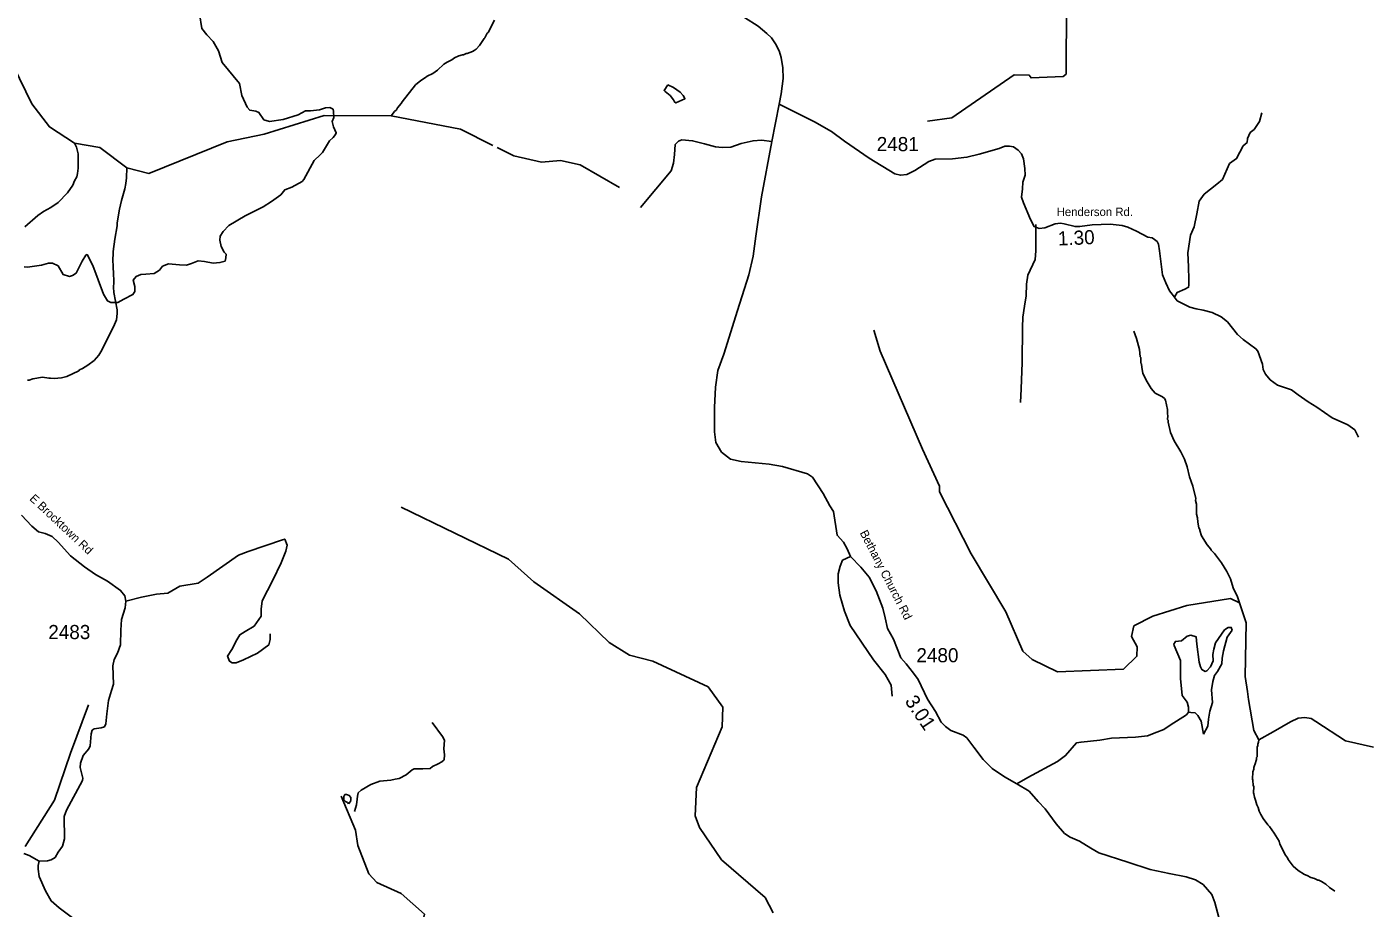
# Model space of a CAD drawing. Extents: x 1248224 to 1454986, y 825081 to 985870.
# Drawn here: x 1367503 to 1379404, y 843465 to 851257 of the extents above; entities that cross this region are included whole.
import ezdxf

# ---------------------------------------------------------------- set-up
doc = ezdxf.new("R2010")
doc.units = 0
for name, color, linetype in [('Exist Hydrographic Creek Single Shore', 7, 'Continuous'), ('Exist Hydrographic Misc Water Feature', 7, 'Continuous'), ('Exist Road Non-System Type 51', 7, 'Continuous'), ('Exist Road Secondary Mileage Hundredths English Label', 7, 'Continuous'), ('Exist Road Secondary Type 41 Attributed', 7, 'Continuous'), ('Exist Road Secondary Type 51 Attributed', 7, 'Continuous'), ('Exist Road Secondary Type 51 Label', 7, 'Continuous'), ('Exist Road Secondary Type 51 Number Label', 7, 'Continuous')]:
    doc.layers.add(name, color=color, linetype=linetype)

msp = doc.modelspace()

# ---------------------------------------------------------------- linework, layer by layer
at = {"layer": 'Exist Hydrographic Creek Single Shore'}
for points in [[(1375464, 850424), (1375681, 850452), (1376231, 850832), (1376364, 850829), (1376381, 850806), (1376664, 850817), (1376690, 850839), (1376694, 851466), (1376756, 851606), (1376925, 851737), (1377506, 852014), (1377613, 852347), (1377809, 852553), (1378241, 852899), (1378437, 853056), (1378476, 853321), (1378519, 853412), (1378866, 853632), (1378977, 853754), (1379062, 854027), (1379105, 854084)], [(1371622, 850209), (1371337, 850352), (1370723, 850470), (1370131, 850472), (1369602, 850309), (1369275, 850240), (1368582, 849960), (1368386, 850010), (1368148, 850190), (1367924, 850229), (1367702, 850373), (1367548, 850576), (1367221, 851243)]]:
    msp.add_lwpolyline(points, dxfattribs=at)
at = {"layer": 'Exist Hydrographic Misc Water Feature'}
for points in [[(1371637, 851315), (1371580, 851207), (1371572, 851201), (1371553, 851161), (1371545, 851154), (1371505, 851093), (1371475, 851061), (1371458, 851048), (1371442, 851040), (1371394, 851021), (1371386, 851021), (1371362, 851010), (1371354, 851010), (1371323, 851001), (1371283, 850982), (1371260, 850966), (1371218, 850945), (1371188, 850926), (1371134, 850873), (1371092, 850846), (1371043, 850822), (1371027, 850808), (1370986, 850783), (1370939, 850744), (1370820, 850595), (1370812, 850579), (1370779, 850540), (1370770, 850524), (1370754, 850509), (1370723, 850470)], [(1373170, 850746), (1373136, 850695), (1373145, 850685), (1373190, 850649), (1373219, 850613), (1373229, 850594), (1373241, 850584), (1373321, 850622), (1373314, 850636), (1373306, 850649), (1373277, 850679), (1373219, 850721), (1373170, 850746)], [(1367486, 849490), (1367600, 849588), (1367649, 849623), (1367714, 849661), (1367779, 849705), (1367863, 849789), (1367908, 849856), (1367925, 849896), (1367944, 849930), (1367951, 849959), (1367956, 850007), (1367957, 850135), (1367942, 850192), (1367924, 850229)], [(1372054, 850062), (1371807, 850117), (1371662, 850189)], [(1367507, 848132), (1367523, 848134), (1367556, 848145), (1367642, 848159), (1367696, 848150), (1367712, 848151), (1367744, 848149), (1367808, 848155), (1367856, 848166), (1367961, 848215), (1367969, 848223), (1367994, 848235), (1368042, 848265), (1368097, 848308), (1368139, 848355), (1368157, 848383), (1368178, 848422), (1368191, 848454), (1368268, 848604), (1368287, 848646), (1368294, 848667), (1368301, 848723), (1368302, 848755), (1368273, 848908), (1368270, 848956), (1368273, 848996), (1368272, 849036), (1368268, 849052), (1368267, 849156), (1368263, 849180), (1368265, 849270), (1368280, 849380), (1368301, 849499), (1368301, 849523), (1368322, 849645), (1368340, 849722), (1368370, 849825), (1368379, 849873), (1368384, 849921), (1368386, 850010)], [(1372742, 849838), (1372395, 850036), (1372221, 850075), (1372054, 850062)], [(1379409, 844888), (1379160, 844943), (1378897, 845115), (1378856, 845142), (1378801, 845151), (1378743, 845144), (1378675, 845113), (1378520, 845024), (1378395, 844951), (1378351, 845036), (1378303, 845308), (1378294, 845380), (1378272, 845512), (1378282, 845988), (1378224, 846165), (1378144, 846201), (1377759, 846140), (1377457, 846047), (1377289, 845959), (1377270, 845867), (1377318, 845774), (1377317, 845692), (1377197, 845576), (1376613, 845555), (1376391, 845662), (1376309, 845735), (1376157, 846083), (1375851, 846598), (1375571, 847145), (1375572, 847195), (1375420, 847523), (1375046, 848390), (1374992, 848575)], [(1377289, 848566), (1377312, 848501), (1377339, 848404), (1377346, 848340), (1377350, 848332), (1377352, 848284), (1377356, 848276), (1377359, 848244), (1377370, 848196), (1377397, 848133), (1377441, 848060), (1377478, 848019), (1377502, 848005), (1377543, 847986), (1377559, 847971), (1377568, 847955), (1377587, 847874), (1377586, 847835), (1377589, 847818), (1377588, 847786), (1377592, 847778), (1377592, 847762), (1377614, 847670), (1377646, 847597), (1377704, 847500), (1377736, 847435), (1377760, 847366), (1377780, 847278), (1377810, 847197), (1377836, 847085), (1377835, 847069), (1377842, 847036), (1377844, 846948), (1377852, 846916), (1377855, 846876), (1377865, 846828), (1377873, 846812), (1377873, 846804), (1377888, 846757), (1377938, 846676), (1377971, 846637), (1377973, 846631), (1378002, 846601), (1378064, 846519), (1378112, 846442), (1378143, 846377), (1378167, 846297), (1378207, 846216), (1378224, 846165)], [(1371985, 846351), (1371762, 846549), (1370813, 847011)], [(1374101, 843423), (1374029, 843559), (1373644, 843892), (1373450, 844178), (1373410, 844280), (1373424, 844530), (1373651, 845067), (1373655, 845241), (1373525, 845420), (1373038, 845647), (1372831, 845700), (1372650, 845812), (1372388, 846067), (1371985, 846351)], [(1367487, 844009), (1367746, 844420), (1367888, 844835), (1368048, 845261)], [(1379067, 843614), (1379020, 843648), (1378988, 843676), (1378949, 843699), (1378925, 843710), (1378917, 843710), (1378886, 843727), (1378854, 843736), (1378822, 843752), (1378798, 843761), (1378741, 843798), (1378698, 843836), (1378655, 843893), (1378648, 843909), (1378630, 843933), (1378581, 844030), (1378573, 844055), (1378531, 844128), (1378490, 844185), (1378475, 844201), (1378432, 844258), (1378411, 844291), (1378396, 844323), (1378388, 844355), (1378377, 844379), (1378366, 844420), (1378355, 844444), (1378351, 844476), (1378348, 844484), (1378349, 844540), (1378345, 844548), (1378342, 844596), (1378338, 844604), (1378340, 844668), (1378349, 844692), (1378349, 844708), (1378357, 844724), (1378358, 844732), (1378375, 844779), (1378375, 844795), (1378379, 844803), (1378381, 844891), (1378386, 844899), (1378386, 844915), (1378392, 844931), (1378395, 844951)], [(1371885, 841911), (1371810, 841936), (1371705, 842072), (1371465, 842169), (1371106, 842528), (1370795, 842777), (1370764, 842876), (1370971, 843207), (1371017, 843412), (1370813, 843594), (1370598, 843690), (1370525, 843767), (1370430, 844019), (1370408, 844154), (1370282, 844455)], [(1370345, 844387), (1370337, 844397), (1370319, 844408), (1370306, 844422), (1370305, 844452), (1370315, 844468), (1370329, 844469), (1370337, 844467), (1370353, 844459), (1370366, 844441), (1370368, 844423), (1370363, 844407), (1370345, 844387)], [(1370345, 844387), (1370337, 844397), (1370319, 844408), (1370306, 844422), (1370305, 844452), (1370315, 844468), (1370329, 844469), (1370337, 844467), (1370353, 844459), (1370366, 844441), (1370368, 844423), (1370363, 844407), (1370345, 844387)]]:
    msp.add_lwpolyline(points, dxfattribs=at)
at = {"layer": 'Exist Road Non-System Type 51'}
for points in [[(1369029, 851372), (1369049, 851242), (1369095, 851188), (1369150, 851127), (1369196, 851046), (1369230, 850942), (1369382, 850756), (1369402, 850650), (1369451, 850546), (1369474, 850520), (1369526, 850511), (1369555, 850500), (1369598, 850436), (1369647, 850419), (1369768, 850439), (1369901, 850480), (1369965, 850514), (1370011, 850514), (1370091, 850523), (1370143, 850540), (1370181, 850543), (1370210, 850529), (1370215, 850508), (1370218, 850456), (1370201, 850419), (1370215, 850373), (1370238, 850321), (1370230, 850304), (1370212, 850278), (1370178, 850249), (1370117, 850146), (1370097, 850126), (1370042, 850074), (1369950, 849906), (1369936, 849889), (1369846, 849840), (1369783, 849817), (1369748, 849771), (1369665, 849713), (1369593, 849667), (1369434, 849586), (1369288, 849501), (1369239, 849449), (1369213, 849406), (1369210, 849371), (1369222, 849314), (1369247, 849265), (1369265, 849247), (1369262, 849216), (1369256, 849184)], [(1377651, 848873), (1377672, 848907), (1377741, 848939), (1377773, 848955), (1377776, 848972), (1377776, 849024), (1377773, 849135), (1377767, 849259), (1377789, 849415), (1377822, 849490), (1377845, 849604), (1377868, 849715), (1377910, 849777), (1378024, 849865), (1378073, 849908), (1378135, 850048), (1378197, 850093), (1378255, 850204), (1378291, 850235), (1378294, 850271), (1378317, 850323), (1378353, 850349), (1378395, 850411), (1378401, 850421), (1378421, 850496)], [(1374088, 850242), (1373998, 850256), (1373923, 850250), (1373818, 850227), (1373727, 850194), (1373649, 850191), (1373590, 850197), (1373493, 850223), (1373388, 850250), (1373294, 850259), (1373265, 850246), (1373235, 850217), (1373229, 850129), (1373219, 850051), (1373199, 849985), (1372929, 849659)], [(1376422, 849508), (1376423, 849452), (1376423, 849276), (1376416, 849201), (1376351, 849061), (1376341, 848983), (1376338, 848878), (1376322, 848787), (1376309, 848689), (1376305, 848598), (1376302, 848288), (1376292, 848057), (1376286, 847936)], [(1369256, 849184), (1369210, 849172), (1369149, 849169), (1369072, 849181), (1369017, 849187), (1368959, 849164), (1368913, 849149), (1368853, 849152), (1368755, 849161), (1368703, 849140), (1368674, 849106), (1368628, 849077), (1368556, 849071), (1368510, 849068), (1368469, 849051), (1368443, 849016), (1368458, 848962), (1368458, 848918), (1368440, 848890), (1368360, 848849), (1368308, 848820), (1368244, 848820), (1368216, 848833), (1368179, 848893), (1368087, 849147), (1368035, 849243), (1368024, 849239), (1367992, 849184), (1367940, 849080), (1367905, 849057), (1367879, 849051), (1367825, 849066), (1367779, 849143), (1367730, 849167), (1367695, 849167), (1367632, 849149), (1367508, 849132), (1367479, 849135)], [(1369655, 845889), (1369655, 845841), (1369641, 845792), (1369542, 845720), (1369418, 845659), (1369353, 845634), (1369319, 845634), (1369295, 845648), (1369278, 845693), (1369315, 845751), (1369360, 845837), (1369387, 845882), (1369432, 845909), (1369511, 845957), (1369573, 846047), (1369573, 846109), (1369583, 846181), (1369676, 846363), (1369751, 846517), (1369792, 846620), (1369803, 846675), (1369782, 846727), (1369762, 846720), (1369460, 846619), (1369374, 846584), (1369096, 846392), (1369017, 846337), (1368855, 846310), (1368749, 846248), (1368650, 846241), (1368516, 846213), (1368379, 846179)], [(1375153, 845338), (1375143, 845436), (1375090, 845531), (1374989, 845660), (1374781, 845963), (1374730, 846089), (1374689, 846231), (1374674, 846342), (1374674, 846421), (1374693, 846488), (1374715, 846541), (1374785, 846575)], [(1376255, 844564), (1376352, 844618), (1376613, 844760), (1376686, 844813), (1376782, 844925), (1376823, 844932), (1376988, 844950), (1377093, 844966), (1377303, 844975), (1377409, 844987), (1377493, 845019), (1377553, 845044), (1377610, 845083), (1377754, 845174), (1377772, 845197), (1377772, 845240), (1377761, 845286), (1377717, 845343), (1377701, 845495), (1377703, 845655), (1377646, 845786), (1377644, 845797), (1377657, 845822), (1377712, 845829), (1377762, 845868), (1377794, 845877), (1377840, 845864), (1377847, 845797), (1377868, 845639), (1377879, 845598), (1377890, 845573), (1377920, 845557), (1377936, 845562), (1377966, 845598), (1377991, 845651), (1377989, 845708), (1377996, 845754), (1378012, 845809), (1378092, 845925), (1378124, 845946), (1378151, 845946), (1378158, 845921), (1378114, 845859), (1378082, 845738), (1378069, 845674), (1378066, 845623), (1378028, 845557), (1378002, 845520), (1377989, 845468), (1377977, 845395), (1377984, 845282), (1377961, 845207), (1377948, 845134), (1377943, 845074), (1377904, 845002)], [(1370399, 844318), (1370418, 844378), (1370423, 844428), (1370425, 844453), (1370432, 844485), (1370459, 844508), (1370544, 844556), (1370624, 844586), (1370720, 844597), (1370759, 844604), (1370793, 844609), (1370857, 844643), (1370908, 844687), (1370926, 844696), (1371002, 844696), (1371068, 844700), (1371089, 844716), (1371139, 844739), (1371171, 844758), (1371192, 844776), (1371196, 844820), (1371189, 844874), (1371196, 844950), (1371178, 844982), (1371086, 845106)], [(1377904, 845002), (1377884, 845117), (1377854, 845169), (1377831, 845192), (1377794, 845195), (1377772, 845197)]]:
    msp.add_lwpolyline(points, dxfattribs=at)
at = {"layer": 'Exist Road Secondary Type 41 Attributed'}
for points in [[(1367455, 846940), (1367546, 846842), (1367606, 846791), (1367664, 846778), (1367728, 846750), (1367780, 846699), (1367889, 846580), (1368012, 846482), (1368110, 846413), (1368217, 846354), (1368331, 846274), (1368368, 846225), (1368379, 846179), (1368371, 846121), (1368340, 846016), (1368334, 845923), (1368330, 845792), (1368304, 845718), (1368275, 845663), (1368263, 845607), (1368270, 845446), (1368252, 845390), (1368224, 845301), (1368211, 845182), (1368202, 845095), (1368188, 845066), (1368160, 845059), (1368099, 845050), (1368081, 845037), (1368071, 845005), (1368063, 844898), (1368050, 844873), (1368001, 844815), (1367977, 844745), (1367974, 844708), (1367998, 844614), (1367994, 844594), (1367854, 844330), (1367833, 844273), (1367836, 844078), (1367817, 844011), (1367781, 843958), (1367753, 843913), (1367717, 843891), (1367686, 843882), (1367612, 843879)], [(1367612, 843879), (1367523, 843929), (1367477, 843946)], [(1376909, 843994), (1376979, 843953), (1377237, 843871), (1377434, 843807), (1377601, 843769), (1377751, 843742), (1377835, 843714), (1377902, 843673), (1377978, 843585), (1378005, 843514), (1378063, 843294)], [(1367612, 843879), (1367602, 843842), (1367602, 843808), (1367611, 843743), (1367668, 843616), (1367718, 843528), (1367789, 843467), (1367917, 843368)]]:
    msp.add_lwpolyline(points, dxfattribs=at)
at = {"layer": 'Exist Road Secondary Type 51 Attributed'}
for points in [[(1372418, 851980), (1372436, 851954), (1372488, 851930), (1372671, 851862), (1372759, 851833), (1372997, 851784), (1373132, 851754), (1373299, 851698), (1373370, 851660), (1373541, 851552), (1373679, 851470), (1373846, 851341), (1373967, 851264), (1374046, 851199), (1374086, 851161), (1374122, 851107), (1374155, 851046), (1374172, 850987), (1374185, 850895), (1374189, 850801), (1374170, 850666), (1374153, 850575)], [(1374153, 850575), (1374088, 850242), (1373997, 849755), (1373948, 849406), (1373924, 849228), (1373886, 849064), (1373784, 848750), (1373664, 848363), (1373611, 848218), (1373591, 848072), (1373582, 847890), (1373582, 847676), (1373593, 847582), (1373643, 847497), (1373722, 847435), (1373818, 847413), (1374064, 847390), (1374184, 847369), (1374404, 847305), (1374448, 847276), (1374542, 847132), (1374603, 847023), (1374633, 846971), (1374665, 846762), (1374721, 846701), (1374756, 846642), (1374785, 846575), (1374876, 846478), (1374949, 846391), (1375010, 846271), (1375069, 846118), (1375092, 846030), (1375110, 845937), (1375165, 845843), (1375230, 845677), (1375277, 845624), (1375341, 845542), (1375382, 845487), (1375464, 845311), (1375537, 845202), (1375587, 845108), (1375625, 845070), (1375672, 845035), (1375781, 844994), (1375813, 844970), (1375874, 844888), (1375956, 844778), (1376038, 844699), (1376146, 844626), (1376255, 844564), (1376363, 844497), (1376442, 844406), (1376504, 844341), (1376603, 844210), (1376676, 844125), (1376726, 844093), (1376808, 844055), (1376909, 843994)], [(1374153, 850575), (1374277, 850512), (1374465, 850417), (1374615, 850333), (1374731, 850247), (1374950, 850095), (1375177, 849958), (1375225, 849945), (1375283, 849953), (1375352, 849987), (1375476, 850068), (1375533, 850087), (1375685, 850089), (1375814, 850104), (1375922, 850131), (1376098, 850183), (1376149, 850202), (1376190, 850202), (1376224, 850196), (1376266, 850166), (1376295, 850133), (1376313, 850090), (1376326, 850004), (1376328, 849946), (1376309, 849884), (1376304, 849825), (1376297, 849752), (1376315, 849702), (1376376, 849554), (1376408, 849491), (1376451, 849475), (1376503, 849480), (1376595, 849516), (1376640, 849520), (1376673, 849516), (1376770, 849491), (1376813, 849493), (1376920, 849507), (1377079, 849512), (1377185, 849502), (1377237, 849487), (1377312, 849450), (1377412, 849396), (1377450, 849391), (1377473, 849378), (1377495, 849360), (1377507, 849337), (1377517, 849276), (1377543, 849065), (1377571, 848993), (1377605, 848922), (1377629, 848892), (1377672, 848835), (1377783, 848778), (1377840, 848764), (1377901, 848753), (1377983, 848731), (1378062, 848692), (1378116, 848649), (1378205, 848538), (1378257, 848493), (1378368, 848411), (1378384, 848388), (1378426, 848273), (1378434, 848226), (1378453, 848187), (1378495, 848137), (1378559, 848090), (1378612, 848072), (1378683, 848046), (1378742, 848004), (1378831, 847940), (1378907, 847895), (1379044, 847801), (1379180, 847737), (1379243, 847693), (1379275, 847628)]]:
    msp.add_lwpolyline(points, dxfattribs=at)

# ---------------------------------------------------------------- texts
at = {"layer": 'Exist Road Secondary Mileage Hundredths English Label'}
for s, rotation, p in [('1.30', 2.3879, (1376620, 849323)), ('3.01', 304.0249, (1375260, 845294))]:
    msp.add_text(s, height=125, rotation=rotation, dxfattribs=at).set_placement(p)
at = {"layer": 'Exist Road Secondary Type 51 Label'}
msp.add_text('Henderson Rd.', height=75, dxfattribs=at).set_placement((1376607, 849584))
for s, rotation, p in [('E Brocktown Rd', 316.7778, (1367521, 847078)), ('Bethany Church Rd', 297.3684, (1374864, 846783))]:
    msp.add_text(s, height=75, rotation=rotation, dxfattribs=at).set_placement(p)
at = {"layer": 'Exist Road Secondary Type 51 Number Label'}
for s, p in [('2481', (1375016, 850158)), ('2483', (1367692, 845843)), ('2480', (1375367, 845638))]:
    msp.add_text(s, height=125, dxfattribs=at).set_placement(p)

doc.saveas('drawing.dxf')
